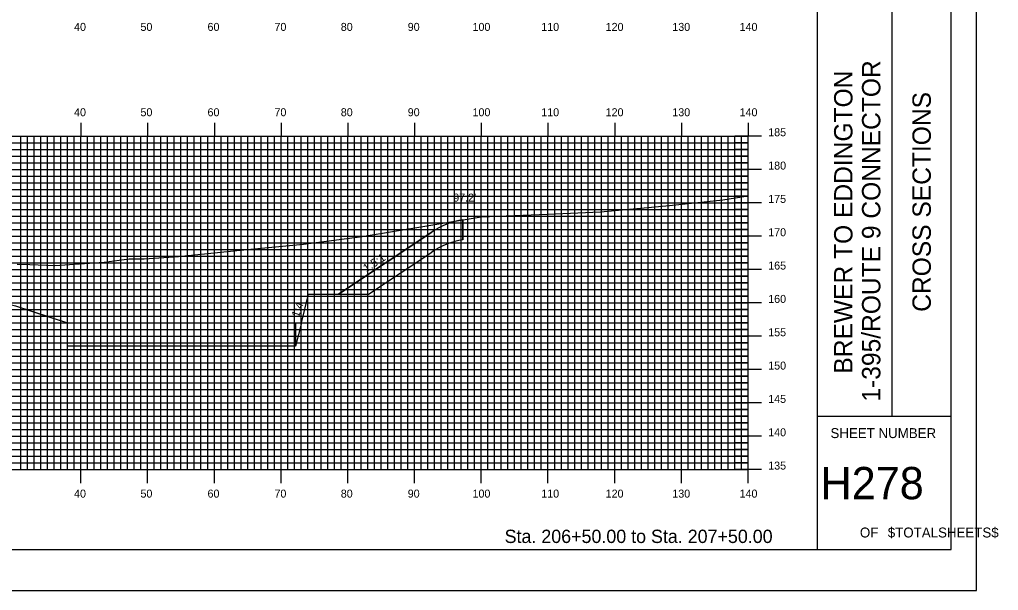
# Model space of a CAD drawing. Extents: x 1793666 to 1794009, y 442591 to 442811.
# Drawn here: x 1793862.1 to 1794008.8, y 442590.5 to 442676.2 of the extents above; entities that cross this region are included whole.
import ezdxf

# ---------------------------------------------------------------- set-up
doc = ezdxf.new("R2010")
doc.units = 0
for name, color, linetype in [('ANNOTATION', 7, 'Continuous'), ('BORDER', 7, 'Continuous'), ('D_Roadway_Centerline', 7, 'Continuous'), ('D_Roadway_FinishedGrade', 7, 'Continuous'), ('D_Roadway_SlopeLines', 7, 'Continuous'), ('D_Text_Standard', 7, 'Continuous'), ('H_V ANNOTATION', 7, 'Continuous'), ('MAJOR', 7, 'Continuous'), ('MINOR', 7, 'Continuous'), ('PLOT BOUNDARY', 7, 'Continuous'), ('S_Roadway_Centerline', 7, 'Continuous')]:
    doc.layers.add(name, color=color, linetype=linetype)

msp = doc.modelspace()

# ---------------------------------------------------------------- linework, layer by layer
at = {"layer": 'ANNOTATION'}
msp.add_line((1793910.79, 442634.97), (1793914.41, 442634.97), dxfattribs=at)
msp.add_line((1793910.79, 442634.97), (1793914.41, 442634.97), dxfattribs=at)
at = {"layer": 'BORDER'}
for p, q in [((1793981.71, 442596.67), (1793981.71, 442806.67)), ((1793992.9, 442616.67), (1793992.9, 442686.67)), ((1793981.71, 442616.67), (1794001.71, 442616.67))]:
    msp.add_line(p, q, dxfattribs=at)
msp.add_lwpolyline([(1793681.71, 442596.67), (1794001.71, 442596.67), (1794001.71, 442806.67), (1793681.71, 442806.67)], close=True, dxfattribs=at)
at = {"layer": 'D_Roadway_Centerline'}
msp.add_lwpolyline([(1793793.81, 442631.3), (1793801.04, 442633.71), (1793808.31, 442636.13), (1793811.31, 442636.25), (1793819.31, 442636.57), (1793831.31, 442636.33), (1793843.31, 442636.09), (1793851.31, 442635.77), (1793861.49, 442633.23), (1793865.39, 442631.95), (1793869.29, 442630.66)], dxfattribs=at)
at = {"layer": 'D_Roadway_FinishedGrade'}
for p, q in [((1793928.57, 442646.13), (1793928.57, 442643.13)), ((1793861.49, 442633.23), (1793869.29, 442630.66)), ((1793861.49, 442633.23), (1793869.29, 442630.66)), ((1793869.29, 442630.66), (1793903.47, 442630.67)), ((1793869.29, 442627.17), (1793869.29, 442630.66))]:
    msp.add_line(p, q, dxfattribs=at)
for points in [[(1793909.91, 442634.97), (1793923.89, 442644.28)], [(1793914.41, 442634.97), (1793923.89, 442641.28)], [(1793903.47, 442630.67), (1793903.47, 442627.17), (1793869.29, 442627.17)]]:
    msp.add_lwpolyline(points, dxfattribs=at)
for centre in [(1793930.54, 442634.3), (1793930.54, 442631.3)]:
    msp.add_arc(centre, 12, 99.467, 123.6872, dxfattribs=at)
at = {"layer": 'D_Roadway_SlopeLines'}
for p, q in [((1793928.57, 442643.13), (1793928.57, 442646.13)), ((1793923.89, 442644.28), (1793909.91, 442634.97)), ((1793914.41, 442634.97), (1793923.89, 442641.28)), ((1793904.35, 442630.67), (1793905.42, 442634.97)), ((1793905.42, 442634.97), (1793910.79, 442634.97)), ((1793909.91, 442634.97), (1793914.41, 442634.97)), ((1793904.35, 442630.67), (1793903.47, 442627.17))]:
    msp.add_line(p, q, dxfattribs=at)
for centre in [(1793930.54, 442634.3), (1793930.54, 442631.3)]:
    msp.add_arc(centre, 12, 99.467, 123.6872, dxfattribs=at)
at = {"layer": 'MAJOR'}
for p, q in [((1793871.31, 442660.67), (1793871.31, 442658.67)), ((1793881.31, 442660.67), (1793881.31, 442658.67)), ((1793891.31, 442660.67), (1793891.31, 442658.67)), ((1793901.31, 442660.67), (1793901.31, 442658.67)), ((1793911.31, 442660.67), (1793911.31, 442658.67)), ((1793921.31, 442660.67), (1793921.31, 442658.67)), ((1793931.31, 442660.67), (1793931.31, 442658.67)), ((1793941.31, 442660.67), (1793941.31, 442658.67)), ((1793951.31, 442660.67), (1793951.31, 442658.67)), ((1793961.31, 442660.67), (1793961.31, 442658.67)), ((1793971.31, 442660.67), (1793971.31, 442658.67)), ((1793691.31, 442658.67), (1793971.31, 442658.67)), ((1793691.31, 442658.67), (1793971.31, 442658.67)), ((1793871.31, 442608.67), (1793871.31, 442658.67)), ((1793881.31, 442608.67), (1793881.31, 442658.67)), ((1793891.31, 442608.67), (1793891.31, 442658.67)), ((1793901.31, 442608.67), (1793901.31, 442658.67)), ((1793911.31, 442608.67), (1793911.31, 442658.67)), ((1793921.31, 442608.67), (1793921.31, 442658.67)), ((1793931.31, 442608.67), (1793931.31, 442658.67)), ((1793941.31, 442608.67), (1793941.31, 442658.67)), ((1793951.31, 442608.67), (1793951.31, 442658.67)), ((1793961.31, 442608.67), (1793961.31, 442658.67)), ((1793973.32, 442658.67), (1793969.31, 442658.67)), ((1793971.31, 442608.67), (1793971.31, 442658.67)), ((1793971.31, 442608.67), (1793971.31, 442658.67)), ((1793691.31, 442653.67), (1793971.31, 442653.67)), ((1793973.32, 442653.67), (1793969.31, 442653.67)), ((1793691.31, 442648.67), (1793971.31, 442648.67)), ((1793973.32, 442648.67), (1793969.31, 442648.67)), ((1793691.31, 442643.67), (1793971.31, 442643.67)), ((1793973.32, 442643.67), (1793969.31, 442643.67)), ((1793691.31, 442638.67), (1793971.31, 442638.67)), ((1793973.32, 442638.67), (1793969.31, 442638.67)), ((1793691.31, 442633.67), (1793971.31, 442633.67)), ((1793973.32, 442633.67), (1793969.31, 442633.67)), ((1793691.31, 442628.67), (1793971.31, 442628.67)), ((1793973.32, 442628.67), (1793969.31, 442628.67)), ((1793691.31, 442623.67), (1793971.31, 442623.67)), ((1793973.32, 442623.67), (1793969.31, 442623.67)), ((1793691.31, 442618.67), (1793971.31, 442618.67)), ((1793973.32, 442618.67), (1793969.31, 442618.67)), ((1793691.31, 442613.67), (1793971.31, 442613.67)), ((1793973.32, 442613.67), (1793969.31, 442613.67)), ((1793691.31, 442608.67), (1793971.31, 442608.67)), ((1793691.31, 442608.67), (1793971.31, 442608.67)), ((1793871.31, 442606.66), (1793871.31, 442608.67)), ((1793881.31, 442606.66), (1793881.31, 442608.67)), ((1793891.31, 442606.66), (1793891.31, 442608.67)), ((1793901.31, 442606.66), (1793901.31, 442608.67)), ((1793911.31, 442606.66), (1793911.31, 442608.67)), ((1793921.31, 442606.66), (1793921.31, 442608.67)), ((1793931.31, 442606.66), (1793931.31, 442608.67)), ((1793941.31, 442606.66), (1793941.31, 442608.67)), ((1793951.31, 442606.66), (1793951.31, 442608.67)), ((1793961.31, 442606.66), (1793961.31, 442608.67)), ((1793973.32, 442608.67), (1793969.31, 442608.67)), ((1793971.31, 442606.66), (1793971.31, 442608.67))]:
    msp.add_line(p, q, dxfattribs=at)
at = {"layer": 'MINOR'}
for p, q in [((1793862.31, 442608.67), (1793862.31, 442658.67)), ((1793863.31, 442608.67), (1793863.31, 442658.67)), ((1793864.31, 442608.67), (1793864.31, 442658.67)), ((1793865.31, 442608.67), (1793865.31, 442658.67)), ((1793866.31, 442608.67), (1793866.31, 442658.67)), ((1793867.31, 442608.67), (1793867.31, 442658.67)), ((1793868.31, 442608.67), (1793868.31, 442658.67)), ((1793869.31, 442608.67), (1793869.31, 442658.67)), ((1793870.31, 442608.67), (1793870.31, 442658.67)), ((1793872.31, 442608.67), (1793872.31, 442658.67)), ((1793873.31, 442608.67), (1793873.31, 442658.67)), ((1793874.31, 442608.67), (1793874.31, 442658.67)), ((1793875.31, 442608.67), (1793875.31, 442658.67)), ((1793876.31, 442608.67), (1793876.31, 442658.67)), ((1793877.31, 442608.67), (1793877.31, 442658.67)), ((1793878.31, 442608.67), (1793878.31, 442658.67)), ((1793879.31, 442608.67), (1793879.31, 442658.67)), ((1793880.31, 442608.67), (1793880.31, 442658.67)), ((1793882.31, 442608.67), (1793882.31, 442658.67)), ((1793883.31, 442608.67), (1793883.31, 442658.67)), ((1793884.31, 442608.67), (1793884.31, 442658.67)), ((1793885.31, 442608.67), (1793885.31, 442658.67)), ((1793886.31, 442608.67), (1793886.31, 442658.67)), ((1793887.31, 442608.67), (1793887.31, 442658.67)), ((1793888.31, 442608.67), (1793888.31, 442658.67)), ((1793889.31, 442608.67), (1793889.31, 442658.67)), ((1793890.31, 442608.67), (1793890.31, 442658.67)), ((1793892.31, 442608.67), (1793892.31, 442658.67)), ((1793893.31, 442608.67), (1793893.31, 442658.67)), ((1793894.31, 442608.67), (1793894.31, 442658.67)), ((1793895.31, 442608.67), (1793895.31, 442658.67)), ((1793896.31, 442608.67), (1793896.31, 442658.67)), ((1793897.31, 442608.67), (1793897.31, 442658.67)), ((1793898.31, 442608.67), (1793898.31, 442658.67)), ((1793899.31, 442608.67), (1793899.31, 442658.67)), ((1793900.31, 442608.67), (1793900.31, 442658.67)), ((1793902.31, 442608.67), (1793902.31, 442658.67)), ((1793903.31, 442608.67), (1793903.31, 442658.67)), ((1793904.31, 442608.67), (1793904.31, 442658.67)), ((1793905.31, 442608.67), (1793905.31, 442658.67)), ((1793906.31, 442608.67), (1793906.31, 442658.67)), ((1793907.31, 442608.67), (1793907.31, 442658.67)), ((1793908.31, 442608.67), (1793908.31, 442658.67)), ((1793909.31, 442608.67), (1793909.31, 442658.67)), ((1793910.31, 442608.67), (1793910.31, 442658.67)), ((1793912.31, 442608.67), (1793912.31, 442658.67)), ((1793913.31, 442608.67), (1793913.31, 442658.67)), ((1793914.31, 442608.67), (1793914.31, 442658.67)), ((1793915.31, 442608.67), (1793915.31, 442658.67)), ((1793916.31, 442608.67), (1793916.31, 442658.67)), ((1793917.31, 442608.67), (1793917.31, 442658.67)), ((1793918.31, 442608.67), (1793918.31, 442658.67)), ((1793919.31, 442608.67), (1793919.31, 442658.67)), ((1793920.31, 442608.67), (1793920.31, 442658.67)), ((1793922.31, 442608.67), (1793922.31, 442658.67)), ((1793923.31, 442608.67), (1793923.31, 442658.67)), ((1793924.31, 442608.67), (1793924.31, 442658.67)), ((1793925.31, 442608.67), (1793925.31, 442658.67)), ((1793926.31, 442608.67), (1793926.31, 442658.67)), ((1793927.31, 442608.67), (1793927.31, 442658.67)), ((1793928.31, 442608.67), (1793928.31, 442658.67)), ((1793929.31, 442608.67), (1793929.31, 442658.67)), ((1793930.31, 442608.67), (1793930.31, 442658.67)), ((1793932.31, 442608.67), (1793932.31, 442658.67)), ((1793933.31, 442608.67), (1793933.31, 442658.67)), ((1793934.31, 442608.67), (1793934.31, 442658.67)), ((1793935.31, 442608.67), (1793935.31, 442658.67)), ((1793936.31, 442608.67), (1793936.31, 442658.67)), ((1793937.31, 442608.67), (1793937.31, 442658.67)), ((1793938.31, 442608.67), (1793938.31, 442658.67)), ((1793939.31, 442608.67), (1793939.31, 442658.67)), ((1793940.31, 442608.67), (1793940.31, 442658.67)), ((1793942.31, 442608.67), (1793942.31, 442658.67)), ((1793943.31, 442608.67), (1793943.31, 442658.67)), ((1793944.31, 442608.67), (1793944.31, 442658.67)), ((1793945.31, 442608.67), (1793945.31, 442658.67)), ((1793946.31, 442608.67), (1793946.31, 442658.67)), ((1793947.31, 442608.67), (1793947.31, 442658.67)), ((1793948.31, 442608.67), (1793948.31, 442658.67)), ((1793949.31, 442608.67), (1793949.31, 442658.67)), ((1793950.31, 442608.67), (1793950.31, 442658.67)), ((1793952.31, 442608.67), (1793952.31, 442658.67)), ((1793953.31, 442608.67), (1793953.31, 442658.67)), ((1793954.31, 442608.67), (1793954.31, 442658.67)), ((1793955.31, 442608.67), (1793955.31, 442658.67)), ((1793956.31, 442608.67), (1793956.31, 442658.67)), ((1793957.31, 442608.67), (1793957.31, 442658.67)), ((1793958.31, 442608.67), (1793958.31, 442658.67)), ((1793959.31, 442608.67), (1793959.31, 442658.67)), ((1793960.31, 442608.67), (1793960.31, 442658.67)), ((1793962.31, 442608.67), (1793962.31, 442658.67)), ((1793963.31, 442608.67), (1793963.31, 442658.67)), ((1793964.31, 442608.67), (1793964.31, 442658.67)), ((1793965.31, 442608.67), (1793965.31, 442658.67)), ((1793966.31, 442608.67), (1793966.31, 442658.67)), ((1793967.31, 442608.67), (1793967.31, 442658.67)), ((1793968.31, 442608.67), (1793968.31, 442658.67)), ((1793969.31, 442608.67), (1793969.31, 442658.67)), ((1793970.31, 442608.67), (1793970.31, 442658.67)), ((1793691.31, 442657.67), (1793971.31, 442657.67)), ((1793971.31, 442657.67), (1793969.31, 442657.67)), ((1793691.31, 442656.67), (1793971.31, 442656.67)), ((1793691.31, 442655.67), (1793971.31, 442655.67)), ((1793971.31, 442656.67), (1793969.31, 442656.67)), ((1793971.31, 442655.67), (1793969.31, 442655.67)), ((1793691.31, 442654.67), (1793971.31, 442654.67)), ((1793971.31, 442654.67), (1793969.31, 442654.67)), ((1793691.31, 442652.67), (1793971.31, 442652.67)), ((1793971.31, 442652.67), (1793969.31, 442652.67)), ((1793691.31, 442651.67), (1793971.31, 442651.67)), ((1793971.31, 442651.67), (1793969.31, 442651.67)), ((1793691.31, 442650.67), (1793971.31, 442650.67)), ((1793691.31, 442649.67), (1793971.31, 442649.67)), ((1793971.31, 442650.67), (1793969.31, 442650.67)), ((1793971.31, 442649.67), (1793969.31, 442649.67)), ((1793691.31, 442647.67), (1793971.31, 442647.67)), ((1793691.31, 442646.67), (1793971.31, 442646.67)), ((1793971.31, 442647.67), (1793969.31, 442647.67)), ((1793971.31, 442646.67), (1793969.31, 442646.67)), ((1793691.31, 442645.67), (1793971.31, 442645.67)), ((1793971.31, 442645.67), (1793969.31, 442645.67)), ((1793691.31, 442644.67), (1793971.31, 442644.67)), ((1793971.31, 442644.67), (1793969.31, 442644.67)), ((1793691.31, 442642.67), (1793971.31, 442642.67)), ((1793971.31, 442642.67), (1793969.31, 442642.67)), ((1793691.31, 442641.67), (1793971.31, 442641.67)), ((1793691.31, 442640.67), (1793971.31, 442640.67)), ((1793971.31, 442641.67), (1793969.31, 442641.67)), ((1793971.31, 442640.67), (1793969.31, 442640.67)), ((1793691.31, 442639.67), (1793971.31, 442639.67)), ((1793971.31, 442639.67), (1793969.31, 442639.67)), ((1793691.31, 442637.67), (1793971.31, 442637.67)), ((1793971.31, 442637.67), (1793969.31, 442637.67)), ((1793691.31, 442636.67), (1793971.31, 442636.67)), ((1793971.31, 442636.67), (1793969.31, 442636.67)), ((1793691.31, 442635.67), (1793971.31, 442635.67)), ((1793971.31, 442635.67), (1793969.31, 442635.67)), ((1793691.31, 442634.67), (1793971.31, 442634.67)), ((1793971.31, 442634.67), (1793969.31, 442634.67)), ((1793691.31, 442632.67), (1793971.31, 442632.67)), ((1793971.31, 442632.67), (1793969.31, 442632.67)), ((1793691.31, 442631.67), (1793971.31, 442631.67)), ((1793691.31, 442630.67), (1793971.31, 442630.67)), ((1793971.31, 442631.67), (1793969.31, 442631.67)), ((1793971.31, 442630.67), (1793969.31, 442630.67)), ((1793691.31, 442629.67), (1793971.31, 442629.67)), ((1793971.31, 442629.67), (1793969.31, 442629.67)), ((1793691.31, 442627.67), (1793971.31, 442627.67)), ((1793971.31, 442627.67), (1793969.31, 442627.67)), ((1793691.31, 442626.67), (1793971.31, 442626.67)), ((1793971.31, 442626.67), (1793969.31, 442626.67)), ((1793691.31, 442625.67), (1793971.31, 442625.67)), ((1793691.31, 442624.67), (1793971.31, 442624.67)), ((1793971.31, 442625.67), (1793969.31, 442625.67)), ((1793971.31, 442624.67), (1793969.31, 442624.67)), ((1793691.31, 442622.67), (1793971.31, 442622.67)), ((1793691.31, 442621.67), (1793971.31, 442621.67)), ((1793971.31, 442622.67), (1793969.31, 442622.67)), ((1793971.31, 442621.67), (1793969.31, 442621.67)), ((1793691.31, 442620.67), (1793971.31, 442620.67)), ((1793971.31, 442620.67), (1793969.31, 442620.67)), ((1793691.31, 442619.67), (1793971.31, 442619.67)), ((1793971.31, 442619.67), (1793969.31, 442619.67)), ((1793691.31, 442617.67), (1793971.31, 442617.67)), ((1793971.31, 442617.67), (1793969.31, 442617.67)), ((1793691.31, 442616.67), (1793971.31, 442616.67)), ((1793691.31, 442615.67), (1793971.31, 442615.67)), ((1793971.31, 442616.67), (1793969.31, 442616.67)), ((1793971.31, 442615.67), (1793969.31, 442615.67)), ((1793691.31, 442614.67), (1793971.31, 442614.67)), ((1793971.31, 442614.67), (1793969.31, 442614.67)), ((1793691.31, 442612.67), (1793971.31, 442612.67)), ((1793691.31, 442611.67), (1793971.31, 442611.67)), ((1793971.31, 442612.67), (1793969.31, 442612.67)), ((1793971.31, 442611.67), (1793969.31, 442611.67)), ((1793691.31, 442610.67), (1793971.31, 442610.67)), ((1793971.31, 442610.67), (1793969.31, 442610.67)), ((1793691.31, 442609.67), (1793971.31, 442609.67)), ((1793971.31, 442609.67), (1793969.31, 442609.67))]:
    msp.add_line(p, q, dxfattribs=at)
at = {"layer": 'PLOT BOUNDARY'}
msp.add_lwpolyline([(1793665.53, 442590.55), (1794005.53, 442590.55), (1794005.53, 442810.55), (1793665.53, 442810.55)], close=True, dxfattribs=at)
at = {"layer": 'S_Roadway_Centerline'}
msp.add_lwpolyline([(1793861.75, 442639.48), (1793863.67, 442639.43), (1793867.39, 442639.29), (1793874.82, 442639.8), (1793878.56, 442640.26), (1793880.78, 442640.29), (1793885.96, 442640.63), (1793894.68, 442641.54), (1793904.65, 442642.5), (1793913.46, 442643.64), (1793923.13, 442645.23), (1793931.32, 442646.59), (1793941.27, 442646.97), (1793949.2, 442647.34), (1793959.52, 442648.27), (1793967.51, 442649.14), (1793971.31, 442649.71)], dxfattribs=at)

# ---------------------------------------------------------------- texts
at = {"layer": 'ANNOTATION'}
for s, rotation, p in [('1.5:1', 32.7629, (1793914.08, 442638.24)), ('1:4', 70.516, (1793903.96, 442631.43)), ('1:4', 70.516, (1793903.96, 442631.43))]:
    msp.add_text(s, height=1.2, rotation=rotation, dxfattribs=at).set_placement(p)
at = {"layer": 'BORDER'}
for s, p in [('1-395/ROUTE 9 CONNECTOR', (1793991.12, 442618.87)), ('BREWER TO EDDINGTON', (1793986.94, 442623.07)), ('CROSS SECTIONS', (1793998.68, 442632.34))]:
    msp.add_text(s, height=2.7557, rotation=90, dxfattribs=at).set_placement(p)
for s, height, p in [('SHEET NUMBER', 1.4905, (1793983.64, 442613.4)), ('H278', 4.839, (1793982.15, 442604.23)), ('OF', 1.491, (1793988.05, 442598.49)), ('$TOTALSHEETS$', 1.4905, (1793992.23, 442598.49))]:
    msp.add_text(s, height=height, dxfattribs=at).set_placement(p)
at = {"layer": 'D_Text_Standard'}
msp.add_text("97.2'", height=1.2, dxfattribs=at).set_placement((1793927.11, 442648.87))
at = {"layer": 'H_V ANNOTATION'}
for s, height, p in [('40', 1.2, (1793870.29, 442674.47)), ('50', 1.2, (1793880.24, 442674.47)), ('60', 1.2, (1793890.29, 442674.47)), ('70', 1.2, (1793900.32, 442674.47)), ('80', 1.2, (1793910.26, 442674.47)), ('90', 1.2, (1793920.29, 442674.47)), ('100', 1.2, (1793930, 442674.47)), ('110', 1.2, (1793940.3, 442674.47)), ('120', 1.2, (1793949.95, 442674.47)), ('130', 1.2, (1793959.94, 442674.47)), ('140', 1.2, (1793970.02, 442674.47)), ('40', 1.2, (1793870.29, 442661.67)), ('50', 1.2, (1793880.24, 442661.67)), ('60', 1.2, (1793890.29, 442661.67)), ('70', 1.2, (1793900.32, 442661.67)), ('80', 1.2, (1793910.26, 442661.67)), ('90', 1.2, (1793920.29, 442661.67)), ('100', 1.2, (1793930, 442661.67)), ('110', 1.2, (1793940.3, 442661.67)), ('120', 1.2, (1793949.95, 442661.67)), ('130', 1.2, (1793959.94, 442661.67)), ('140', 1.2, (1793970.02, 442661.67)), ('185', 1.2, (1793974.31, 442658.67)), ('180', 1.2, (1793974.31, 442653.67)), ('175', 1.2, (1793974.31, 442648.67)), ('170', 1.2, (1793974.31, 442643.67)), ('165', 1.2, (1793974.31, 442638.67)), ('160', 1.2, (1793974.31, 442633.67)), ('155', 1.2, (1793974.31, 442628.67)), ('150', 1.2, (1793974.31, 442623.67)), ('145', 1.2, (1793974.31, 442618.67)), ('140', 1.2, (1793974.31, 442613.67)), ('135', 1.2, (1793974.31, 442608.67)), ('40', 1.2, (1793870.29, 442604.47)), ('50', 1.2, (1793880.24, 442604.47)), ('60', 1.2, (1793890.29, 442604.47)), ('70', 1.2, (1793900.32, 442604.47)), ('80', 1.2, (1793910.26, 442604.47)), ('90', 1.2, (1793920.29, 442604.47)), ('100', 1.2, (1793930, 442604.47)), ('110', 1.2, (1793940.3, 442604.47)), ('120', 1.2, (1793949.95, 442604.47)), ('130', 1.2, (1793959.94, 442604.47)), ('140', 1.2, (1793970.02, 442604.47)), ('Sta. 206+50.00 to Sta. 207+50.00', 2.0004, (1793934.81, 442597.66))]:
    msp.add_text(s, height=height, dxfattribs=at).set_placement(p)

doc.saveas('drawing.dxf')
